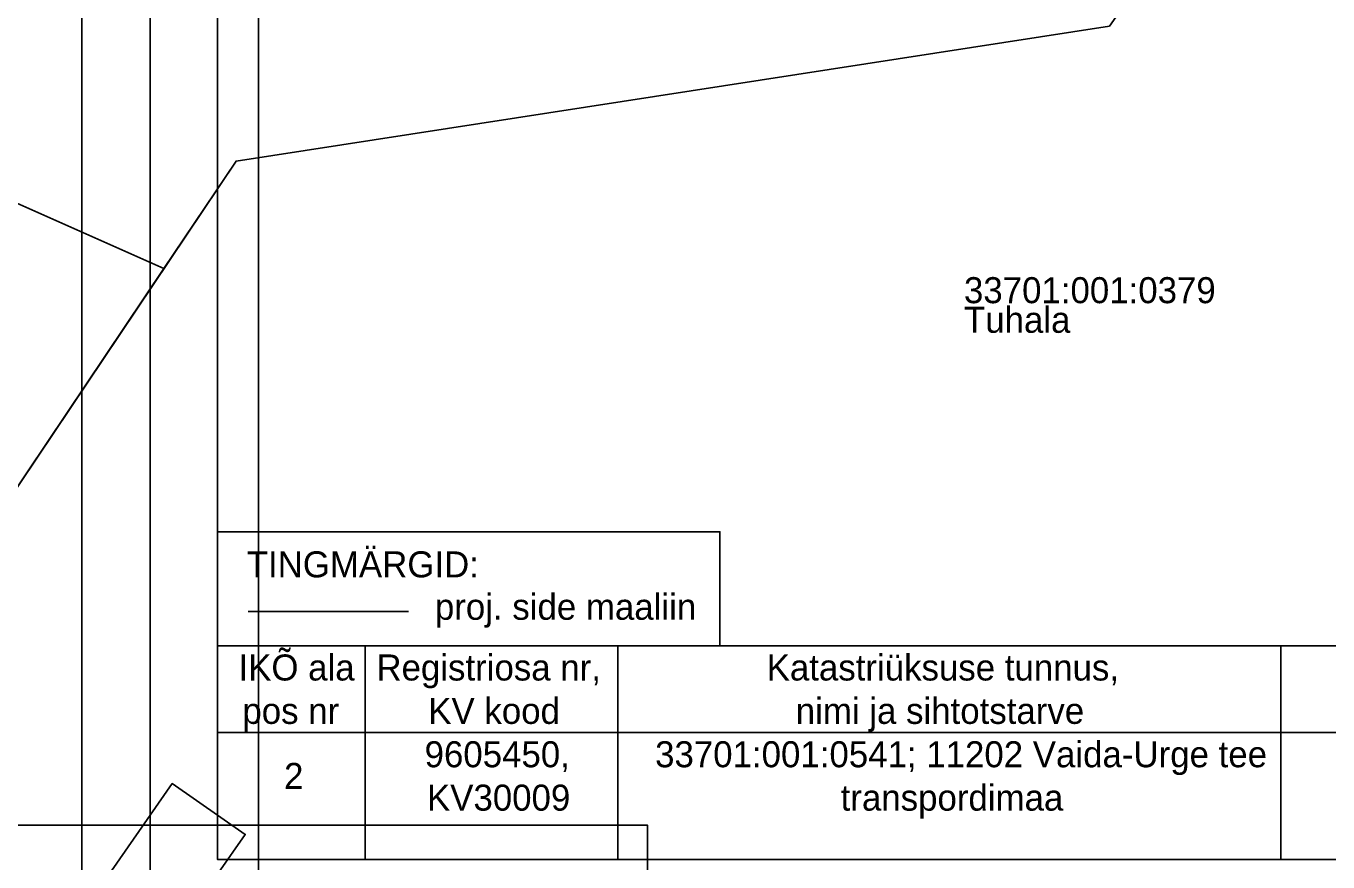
# Model space of a CAD drawing. Extents: x 554947 to 555436, y 6564938 to 6565792.
# Drawn here: x 555187.9 to 555307.9, y 6565441.5 to 6565518.6 of the extents above; entities that cross this region are included whole.
import ezdxf

# ---------------------------------------------------------------- set-up
doc = ezdxf.new("R2010")
doc.units = 0
for name, color, linetype in [('Hoone Vare', 7, 'Continuous'), ('PIIR', 7, 'Continuous'), ('VORMISTUS_1', 7, 'Continuous'), ('VORMISTUS_2', 7, 'Continuous'), ('VORMISTUS_3', 7, 'Continuous')]:
    doc.layers.add(name, color=color, linetype=linetype)

msp = doc.modelspace()

# ---------------------------------------------------------------- linework, layer by layer
at = {"layer": 'Hoone Vare'}
msp.add_lwpolyline([(555191.47, 6565434.45), (555201.41, 6565448.73), (555208.13, 6565444.05), (555198.18, 6565429.78), (555195.48, 6565430.03), (555192.76, 6565431.76)], close=True, dxfattribs=at)
at = {"layer": 'PIIR'}
for points in [[(555121.18, 6565602.26), (555138.98, 6565580.6), (555179.42, 6565586.32), (555242.37, 6565583.94), (555302.6, 6565539.71), (555287.77, 6565518.56), (555207.29, 6565506.14), (555200.64, 6565496.23), (555185.97, 6565502.75), (555177.68, 6565506.44), (555171.49, 6565510.85), (555162.05, 6565514.45), (555140.65, 6565513.25), (555139.49, 6565523.98), (555139.26, 6565529.51), (555141.68, 6565537.52), (555139.64, 6565543.1), (555131.01, 6565550.06), (555126.35, 6565558.74), (555119.63, 6565564.84), (555105.26, 6565587.71), (555099.5, 6565594.91), (555116.17, 6565610.5)], [(555153.01, 6565448.47), (555161.15, 6565451.45), (555173.66, 6565456.03), (555207.29, 6565506.14), (555287.77, 6565518.56), (555302.6, 6565539.71), (555343.14, 6565512.46), (555319.44, 6565481.04), (555323.07, 6565461.26), (555312.9, 6565433.84), (555316.84, 6565372.52), (555318.72, 6565342.57), (555320.51, 6565314.61), (555303.13, 6565302.54), (555208.78, 6565303.3), (555205.15, 6565297.11), (555200.72, 6565310.3), (555206.9, 6565339.44), (555221.23, 6565376.06), (555216.83, 6565392.35), (555207.22, 6565406.57)], [(555140.65, 6565513.25), (555162.05, 6565514.45), (555171.49, 6565510.85), (555177.68, 6565506.44), (555185.97, 6565502.75), (555200.64, 6565496.23), (555173.66, 6565456.03), (555161.15, 6565451.45), (555153.01, 6565448.47), (555143.93, 6565463.6), (555141.65, 6565472.71), (555141.53, 6565491.02), (555142.13, 6565499.56)]]:
    msp.add_lwpolyline(points, close=True, dxfattribs=at)
at = {"layer": 'VORMISTUS_1'}
msp.add_lwpolyline([(555035.19, 6565444.91), (555245.19, 6565444.91), (555245.19, 6565147.91), (555035.19, 6565147.91)], close=True, dxfattribs=at)
at = {"layer": 'VORMISTUS_2'}
for points in [[(554999.36, 6565654.91), (555209.36, 6565654.91), (555209.36, 6565357.91), (554999.36, 6565357.91)], [(555009.36, 6565368.91), (555199.36, 6565368.91), (555199.36, 6565643.91), (555009.36, 6565643.91)], [(555009.36, 6565643.91), (555199.36, 6565643.91), (555199.36, 6565368.91), (555009.36, 6565368.91)]]:
    msp.add_lwpolyline(points, close=True, dxfattribs=at)
at = {"layer": 'VORMISTUS_3'}
for p, q in [((555223.17, 6565464.6), (555208.39, 6565464.6)), ((555219.17, 6565461.44), (555219.17, 6565441.75)), ((555219.17, 6565461.44), (555219.17, 6565441.75)), ((555242.47, 6565461.44), (555242.47, 6565441.75)), ((555242.47, 6565461.44), (555242.47, 6565441.75)), ((555303.57, 6565461.44), (555303.57, 6565441.75)), ((555303.57, 6565461.44), (555303.57, 6565441.75)), ((555205.57, 6565453.44), (555370.57, 6565453.44))]:
    msp.add_line(p, q, dxfattribs=at)
for points in [[(555193.07, 6565415.75), (555383.07, 6565415.75), (555383.07, 6565690.75), (555193.07, 6565690.75)], [(555193.07, 6565690.75), (555383.07, 6565690.75), (555383.07, 6565415.75), (555193.07, 6565415.75)], [(555370.57, 6565441.75), (555205.57, 6565441.75), (555205.57, 6565651.75), (555370.57, 6565651.75)], [(555205.57, 6565471.95), (555251.87, 6565471.95), (555251.87, 6565461.44), (555205.57, 6565461.44)], [(555205.57, 6565461.44), (555370.57, 6565461.44), (555370.57, 6565441.75), (555205.57, 6565441.75)]]:
    msp.add_lwpolyline(points, close=True, dxfattribs=at)

# ---------------------------------------------------------------- texts
at = {"layer": 'PIIR'}
for s, p in [('33701:001:0379', (555274.36, 6565493.03)), ('Tuhala', (555274.36, 6565490.3))]:
    msp.add_text(s, height=2.4, dxfattribs=at).set_placement(p)
at = {"layer": 'VORMISTUS_3'}
for s, p in [('TINGMÄRGID:', (555208.27, 6565467.75)), ('proj. side maaliin', (555225.61, 6565463.84)), ('IKÕ ala', (555207.51, 6565458.24)), ('Registriosa nr,', (555220.22, 6565458.24)), ('Katastriüksuse tunnus,', (555256.18, 6565458.24)), ('KV kood', (555225, 6565454.24)), ('nimi ja sihtotstarve', (555258.86, 6565454.24)), ('pos nr', (555207.87, 6565454.24)), ('9605450,', (555224.66, 6565450.24)), ('33701:001:0541; 11202 Vaida-Urge tee', (555245.9, 6565450.24)), ('2', (555211.71, 6565448.24)), ('KV30009', (555224.88, 6565446.24)), ('transpordimaa', (555263, 6565446.24))]:
    msp.add_text(s, height=2.4, dxfattribs=at).set_placement(p)

doc.saveas('drawing.dxf')
